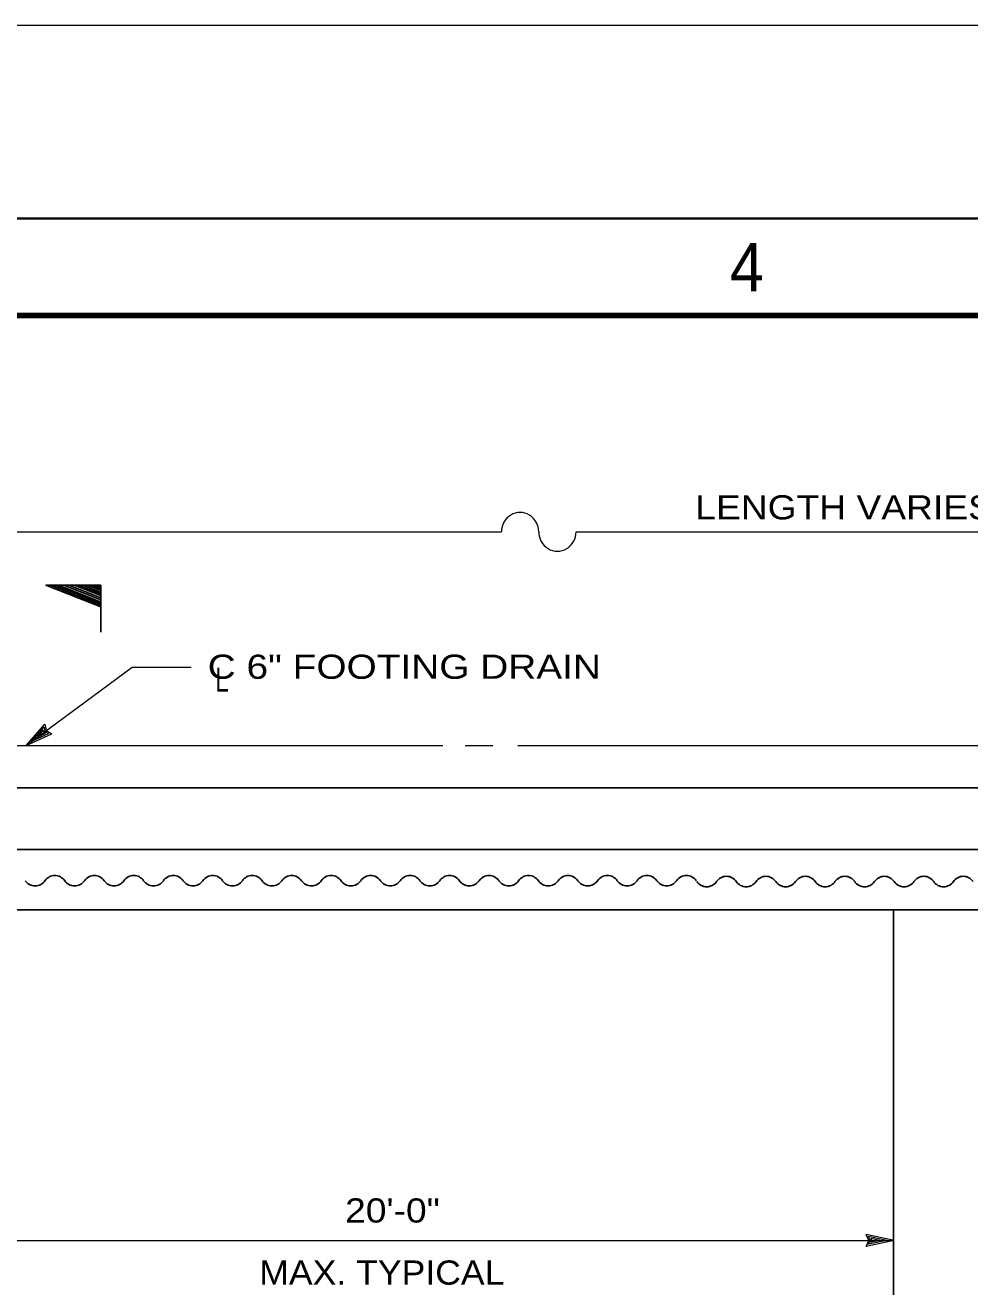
# Model space of a CAD drawing. Extents: x -24.3 to 17.7, y -17.6 to 12.4.
# Drawn here: x -15.32 to -10.43, y 5.87 to 12.39 of the extents above; entities that cross this region are included whole.
import ezdxf
from ezdxf.enums import TextEntityAlignment as Align

# ---------------------------------------------------------------- set-up
doc = ezdxf.new("R2010")
doc.units = 0
doc.header["$LTSCALE"] = 0.05
doc.layers.add('1', color=7, linetype='Continuous', lineweight=13)
doc.layers.add('2', color=7, linetype='Continuous', lineweight=13)

msp = doc.modelspace()

# ---------------------------------------------------------------- linework, layer by layer
at = {"layer": '1'}
for p, q in [((-18.37069, 9.7704), (-12.85569, 9.7704)), ((-12.46869, 9.7704), (-5.40569, 9.7704)), ((-15.31169, 8.6664), (-14.76369, 9.0704)), ((-14.76369, 9.0704), (-14.45769, 9.0704)), ((-15.31169, 8.6664), (-15.21369, 8.7764)), ((-15.28169, 8.6884), (-15.21769, 8.7604)), ((-15.25269, 8.7094), (-15.22269, 8.7444)), ((-15.22269, 8.7444), (-15.21969, 8.7344)), ((-15.21769, 8.7604), (-15.21369, 8.7384)), ((-15.31169, 8.6664), (-15.17769, 8.7264)), ((-15.28169, 8.6884), (-15.19469, 8.7284)), ((-15.25269, 8.7094), (-15.21169, 8.7294)), ((-15.21969, 8.7344), (-15.21169, 8.7294)), ((-15.21369, 8.7384), (-15.19469, 8.7284)), ((-17.71969, 8.6664), (-13.15669, 8.6664)), ((-13.04269, 8.6664), (-12.89969, 8.6664)), ((-12.77069, 8.6664), (-8.43669, 8.6664)), ((-10.82569, 6.1074), (-10.96969, 6.1384)), ((-10.82569, 6.1074), (-10.96969, 6.0764)), ((-10.86269, 6.1074), (-10.95669, 6.1274)), ((-10.94769, 6.1074), (-10.95669, 6.1274)), ((-10.86269, 6.1074), (-10.95669, 6.0874)), ((-10.95669, 6.0874), (-10.94769, 6.1074)), ((-10.89869, 6.1074), (-10.94369, 6.1164)), ((-10.93969, 6.1074), (-10.94369, 6.1164)), ((-10.89869, 6.1074), (-10.94369, 6.0974)), ((-10.94369, 6.0974), (-10.93969, 6.1074))]:
    msp.add_line(p, q, dxfattribs=at)
at = {"layer": '1', "lineweight": 25}
for p, q in [((-18.37569, 8.4474), (-9.74369, 8.4474)), ((-18.37569, 8.1284), (-9.77669, 8.1284)), ((-18.37569, 7.8164), (-9.81169, 7.8164)), ((-10.82769, 1.6764), (-10.82769, 7.8164))]:
    msp.add_line(p, q, dxfattribs=at)
at = {"layer": '1'}
for points in [[(-24.34269, 12.3894), (17.65731, 12.3894), (17.65731, -17.6106)], [(-15.21369, 8.7764), (-15.20669, 8.7434), (-15.17769, 8.7264)], [(-10.96969, 6.0764), (-10.95569, 6.1074), (-10.96969, 6.1384)], [(-18.37569, 6.1074), (-15.84169, 6.1074), (-10.82569, 6.1074)]]:
    msp.add_lwpolyline(points, dxfattribs=at)
at = {"layer": '1', "lineweight": 40}
msp.add_lwpolyline([(-23.34269, -16.6106), (-23.34269, 11.3894), (16.65731, 11.3894), (16.65731, -16.6106)], close=True, dxfattribs=at)
at = {"layer": '1', "lineweight": 90}
msp.add_lwpolyline([(-21.84269, 10.8894), (16.15731, 10.8894), (16.15731, -16.1106), (-21.84269, -16.1106)], close=True, dxfattribs=at)
at = {"layer": '1', "lineweight": 25}
for centre, start, end in [((-15.26469, 8.0009), 214.07719, 325.9228), ((-15.16269, 7.9319), 34.07719, 145.9228), ((-15.06069, 8.0009), 214.07719, 325.9228), ((-14.95869, 7.9319), 34.07719, 145.9228), ((-14.85669, 8.0009), 214.07719, 325.9228), ((-14.75469, 7.9319), 34.07719, 145.9228), ((-14.65269, 8.0009), 214.07719, 325.9228), ((-14.55069, 7.9319), 34.07719, 145.9228), ((-14.44869, 8.0009), 214.07719, 325.9228), ((-14.34669, 7.9319), 34.07719, 145.9228), ((-14.24469, 8.0009), 214.07719, 325.9228), ((-14.14269, 7.9319), 34.07719, 145.9228), ((-14.04069, 8.0009), 214.07719, 325.9228), ((-13.93869, 7.9319), 34.07719, 145.9228), ((-13.83669, 8.0009), 214.07719, 325.9228), ((-13.73469, 7.9319), 34.07719, 145.9228), ((-13.63269, 8.0009), 214.07719, 325.9228), ((-13.53069, 7.9319), 34.07719, 145.9228), ((-13.42869, 8.0009), 214.07719, 325.9228), ((-13.32669, 7.9319), 34.07719, 145.9228), ((-13.22469, 8.0009), 214.07719, 325.9228), ((-13.12269, 7.9319), 34.07719, 145.9228), ((-13.02069, 8.0009), 214.07719, 325.9228), ((-12.91869, 7.9319), 34.07719, 145.9228), ((-12.81669, 8.0009), 214.07719, 325.9228), ((-12.71469, 7.9319), 34.07719, 145.9228), ((-12.61269, 8.0009), 214.07719, 325.9228), ((-12.51069, 7.9319), 34.07719, 145.9228), ((-12.40869, 8.0009), 214.07719, 325.9228), ((-12.30669, 7.9319), 34.07719, 145.9228), ((-12.20469, 8.0009), 214.07719, 325.9228), ((-12.10269, 7.9319), 34.07719, 145.9228), ((-12.00069, 8.0009), 214.07719, 325.9228), ((-11.89869, 7.9319), 34.07719, 145.9228), ((-11.79369, 7.9969), 214.07719, 325.9228), ((-11.69169, 7.9279), 34.07719, 145.9228), ((-11.58969, 7.9969), 214.07719, 325.9228), ((-11.48769, 7.9279), 34.07719, 145.9228), ((-11.38569, 7.9969), 214.07719, 325.9228), ((-11.28369, 7.9279), 34.07719, 145.9228), ((-11.18169, 7.9969), 214.07719, 325.9228), ((-11.07969, 7.9279), 34.07719, 145.9228), ((-10.97769, 7.9969), 214.07719, 325.9228), ((-10.87569, 7.9279), 34.07719, 145.9228), ((-10.77369, 7.9969), 214.07719, 325.9228), ((-10.67169, 7.9279), 34.07719, 145.9228), ((-10.56969, 7.9969), 214.07719, 325.9228), ((-10.46769, 7.9279), 34.07719, 145.9228)]:
    msp.add_arc(centre, 0.06157, start, end, dxfattribs=at)
at = {"layer": '1'}
for centre, major_axis in [((-12.75819, 9.7704), (0, -0.10003)), ((-12.56519, 9.7704), (0, 0.10003))]:
    msp.add_ellipse(centre, major_axis=major_axis, ratio=0.964676, start_param=1.5707963, end_param=4.712389, dxfattribs=at)
at = {"layer": '2', "lineweight": 25}
for p, q in [((-15.18569, 9.4944), (-14.92469, 9.3914)), ((-15.16069, 9.4944), (-14.92469, 9.4004)), ((-15.14369, 9.4944), (-14.92469, 9.4074)), ((-15.11669, 9.4944), (-14.92469, 9.4184)), ((-15.09069, 9.4944), (-14.92469, 9.4284)), ((-15.06069, 9.4944), (-14.92469, 9.4404)), ((-15.03969, 9.4944), (-14.92469, 9.4484)), ((-15.01569, 9.4944), (-14.92469, 9.4574)), ((-14.99469, 9.4944), (-14.92469, 9.4664)), ((-14.97269, 9.4944), (-14.92469, 9.4754)), ((-14.95769, 9.4944), (-14.92469, 9.4814)), ((-14.93769, 9.4944), (-14.92469, 9.4894)), ((-14.92469, 9.4944), (-14.92469, 9.2514))]:
    msp.add_line(p, q, dxfattribs=at)
msp.add_lwpolyline([(-14.92469, 9.4944), (-15.20869, 9.4944), (-14.92469, 9.3824)], dxfattribs=at)

# ---------------------------------------------------------------- texts
at = {"layer": '1'}
for s, height, width, p in [('4', 0.25, 0.95, (-11.58619, 11.0144)), ('20\'-0"', 0.125, 1.15, (-13.41769, 6.1994)), ('MAX. TYPICAL', 0.125, 1.1, (-13.47269, 5.8784))]:
    msp.add_text(s, height=height, dxfattribs=dict(at, width=width)).set_placement(p, align=Align.CENTER)
for s, width, p in [('LENGTH VARIES-SEE NOTE 1', 1.15, (-11.85269, 9.8344)), ('C 6" FOOTING DRAIN', 1.2, (-14.37269, 9.0104)), ('L', 0.75, (-14.33369, 8.9434))]:
    msp.add_text(s, height=0.125, dxfattribs=dict(at, width=width)).set_placement(p)

doc.saveas('drawing.dxf')
